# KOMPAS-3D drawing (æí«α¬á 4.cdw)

Views: Вид 1
Referenced files: Редуктор сборка.cdw
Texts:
  Редуктор соосный. Сборочный чертёж
  Яковлев Д.А.
  Курсовая по деталям машин.
  Noncommercial version
  Js9
  Технические характеристики
  Крутящий момент на выходном валу - 170 Н м.
  Частота вращения тихоходноговала - 60,2 об/мин.
  Общее передаточное число редуктора - 24.
  Степень точности изготовления зубчатой передачи 7-С.
  Расчётный КПД - 0,932.
  Расчётный срок службы редуктора - 8000 часов.
  Технические требования
  Размеры для справок.
  Плоскость разъёма покрыть щелочным лаком или пастой
  "Герметик" У30-М, МрТУ. Применение прокладок не допускается.
  После сборки в редуктор залить масло индустриальное И-50
  ГОСТ 20799-88. Редуктор обкатать без нагрузки в течении двух
  часов. При обнаружении перегрева, ударов и шумов в зацеплении,
  нарушение геометричности и т.д. - устранить дефекты в
  процессе обработки.
  Сборку, приёмку и консервацию редуктора производить по
  заводским тех. требованиям.
  Резьбовые соединения винтов поз.30 уплотнить пастой
  "Герметик" У30-М.
  Болт М8 х 40 ГОСТ 15589-70
  Болт
  ГОСТ
  Шпонка 14 х 9 х 56 ГОСТ 23360-78
  Шпонка
  Штифт 5 х 36 ГОСТ 3128-70
  Штифт
  Хим.Окс.прм
  Шайба 10 Н ГОСТ 6402-70
  Шайба пружинная
  Шайба
  Мaнжета 1-32 х 52-1 ГОСТ 8752-79
  Манжета
  Мaнжета
  Мaнжета 1-58 х 80-1 ГОСТ 8752-79
  Подшипник 36207  ГОСТ 831-75
  Подшипник
  Подшипник 66408  ГОСТ 831-75
  Подшипник 36212  ГОСТ 831-75
  Винт М10 х 45 ГОСТ 1491-80
  Винт
  ДГТУ
  Редуктор соосный.
  Сборочный чертёж
Dimensions and other numbers on the sheet: 495; 30; 10; 56; 16; 8,5; 2 отв.; 8; 65; 18; 14; 45; 160; 72; 35; 32; 110; 60; 58; 80; 52; 169; 21; 4 отв.; 328; 292; 23; 26; 77; 185; 132; 154; 27; 172; 512; 270; 553; 370; 464; 24; 125; 1; 4; 5; 25; 6; 28; 34; 7; 11; 42; 12; 13; 46; 15; 17; 19; 20; 9; 43; 47; 40; 37; 38; -6g; 70; 78; 65Г; 029; 75; 1:2; 59,3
